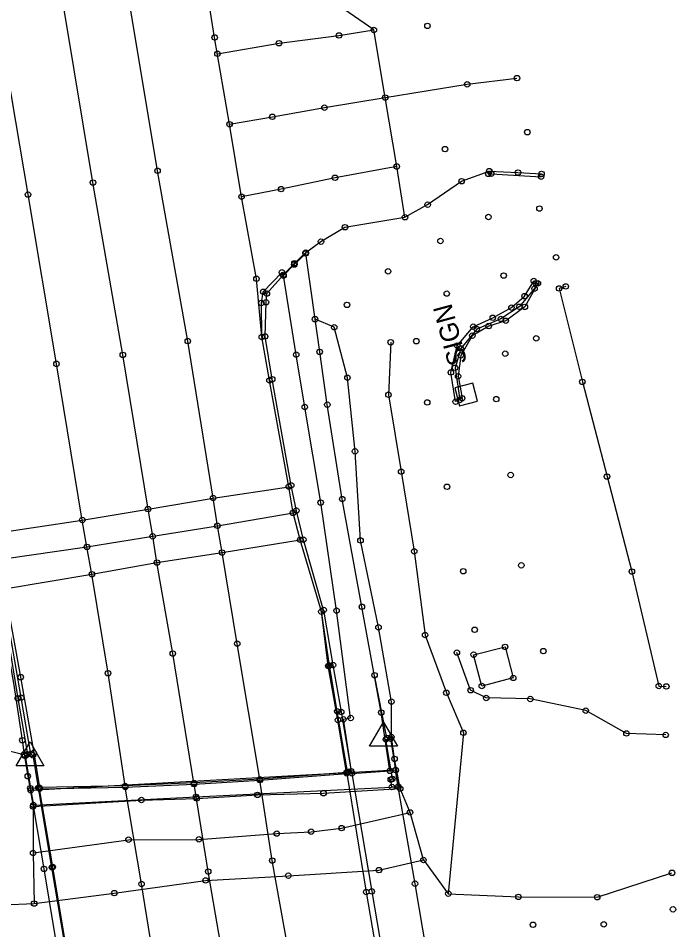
# Model space of a CAD drawing. Extents: x 21481721 to 21494985, y 8063982 to 8084842.
# Drawn here: x 21488058.9 to 21488179.5, y 8075357 to 8075524.3 of the extents above; entities that cross this region are included whole.
import ezdxf

# ---------------------------------------------------------------- set-up
doc = ezdxf.new("R2010")
doc.units = 0
for name, color, linetype in [('Bridge', 7, 'Continuous'), ('Default', 7, 'Continuous'), ('EXT_BL', 7, 'Continuous'), ('EXT_C', 7, 'Continuous'), ('EXT_CON', 7, 'Continuous'), ('EXT_CU', 7, 'Continuous'), ('EXT_D', 7, 'Continuous'), ('EXT_ENT', 7, 'Continuous'), ('EXT_EP', 7, 'Continuous'), ('EXT_GU', 7, 'Continuous'), ('EXT_SWK', 7, 'Continuous'), ('Roadways', 7, 'Continuous'), ('SurControl', 7, 'Continuous'), ('SurPointsNonDTM', 7, 'Continuous'), ('SurRoadPoints', 7, 'Continuous'), ('SurSurveyPoints', 7, 'Continuous'), ('Wall', 7, 'Continuous')]:
    doc.layers.add(name, color=color, linetype=linetype)

msp = doc.modelspace()

# ---------------------------------------------------------------- linework, layer by layer
at = {"layer": 'Bridge'}
for points in [[(21488069.33, 8075343.94), (21488065.2, 8075368.55), (21488062.8, 8075382.91), (21488078.51, 8075383.22), (21488091.12, 8075383.76), (21488103.21, 8075384.48), (21488119.14, 8075385.72), (21488122.72, 8075363.95), (21488125.61, 8075347.18)], [(21488120.08, 8075385.72), (21488123.73, 8075364.06), (21488126.6, 8075347.14), (21488129.6, 8075329.59), (21488132.36, 8075313.39), (21488135.39, 8075295.32), (21488138.2, 8075278.59), (21488141.09, 8075261.71), (21488143.79, 8075245.75), (21488146.67, 8075228.8), (21488149.29, 8075213.2), (21488149.78, 8075209.03)], [(21488108, 8075207.36), (21488103.64, 8075232.31), (21488099.01, 8075261.23), (21488094.1, 8075289.47), (21488089.69, 8075316), (21488085.29, 8075341.96), (21488081.5, 8075365.43), (21488078.51, 8075383.22)], [(21488133.02, 8075208.53), (21488127.97, 8075236.87), (21488123.23, 8075263.68), (21488118.73, 8075292.88), (21488114.06, 8075318.67), (21488109.96, 8075344.62), (21488105.47, 8075369.72), (21488103.21, 8075384.48)], [(21488157.46, 8075212.67), (21488154.44, 8075230.46), (21488151.63, 8075247.26), (21488148.78, 8075264.05), (21488145.96, 8075280.82), (21488143.17, 8075297.55), (21488140.18, 8075315.22), (21488137.31, 8075331.99), (21488134.49, 8075348.81), (21488131.67, 8075365.48), (21488128.59, 8075383.27)], [(21488091.01, 8075206.3), (21488087.47, 8075227.14), (21488083.52, 8075250.23), (21488079.53, 8075273.88), (21488075.57, 8075297.2), (21488071.55, 8075321.1), (21488067.69, 8075343.72), (21488063.6, 8075368.19), (21488061.09, 8075383)], [(21488091.84, 8075206.37), (21488092.44, 8075206.59), (21488088.9, 8075227.4), (21488084.96, 8075250.55), (21488081, 8075274.15), (21488077.07, 8075297.44), (21488073.03, 8075321.28), (21488069.2, 8075343.93), (21488065.05, 8075368.47), (21488062.58, 8075383.09)]]:
    msp.add_lwpolyline(points, dxfattribs=at)
at = {"layer": 'Default'}
msp.add_line((21488061.03, 8075388.55), (21488061.03, 8075388.55), dxfattribs=at)
for points in [[(21488128.12, 8075386.33), (21488061.16, 8075382.6)], [(21488120.76, 8075207.97), (21488116.18, 8075234.47), (21488111.59, 8075262.1), (21488106.7, 8075291.13), (21488102.31, 8075316.99), (21488098.02, 8075342.81), (21488093.73, 8075367.7), (21488091.12, 8075383.76)]]:
    msp.add_lwpolyline(points, dxfattribs=at)
at = {"layer": 'EXT_BL'}
for points in [[(21488103.19, 8075384.64), (21488099.05, 8075409.52), (21488096.27, 8075426.26), (21488095.42, 8075431.16), (21488094.63, 8075436.26), (21488089.97, 8075465.06), (21488084.43, 8075496.32), (21488079.26, 8075527.2), (21488073.87, 8075558.48), (21488069.05, 8075586.55), (21488064.17, 8075616.87), (21488059.01, 8075646.31)], [(21488078.47, 8075383.41), (21488075.34, 8075404.11), (21488072.38, 8075422.27), (21488071.48, 8075427.29), (21488070.62, 8075432.22), (21488065.88, 8075460.89), (21488060.66, 8075491.95), (21488055.28, 8075523.45), (21488049.96, 8075553.99), (21488045.13, 8075582.91), (21488040.13, 8075611.89), (21488034.92, 8075642.89)], [(21488001.98, 8075638.33), (21488003.4, 8075630.75), (21488005.67, 8075621.9), (21488010.36, 8075616.83), (21488017, 8075610.19), (21488020.09, 8075597.51), (21488023.57, 8075574.98), (21488028.19, 8075550.29), (21488031.96, 8075525.57), (21488036.19, 8075501.31), (21488039.36, 8075478.97), (21488044.58, 8075454.12), (21488049.02, 8075430.98), (21488050.89, 8075415.65), (21488053.69, 8075400.59), (21488055.28, 8075390.26), (21488059.93, 8075389.21)], [(21488012.49, 8075527.74), (21488015.17, 8075504.07), (21488014.9, 8075482.37), (21488015.76, 8075463.18), (21488016.7, 8075438.32), (21488019.73, 8075416.24), (21488021.87, 8075392.73), (21488028.33, 8075373.25), (21488035.17, 8075361.28), (21488044.66, 8075361.1), (21488061.79, 8075361.83), (21488076.5, 8075363.75), (21488093.24, 8075366.07), (21488108.43, 8075366.94), (21488125.06, 8075367.97), (21488133.21, 8075369.83), (21488137.78, 8075363.64), (21488150.64, 8075363.06), (21488165.1, 8075362.99), (21488178.82, 8075367.47)], [(21488127.33, 8075392.4), (21488127.35, 8075398.88), (21488124.97, 8075412.53), (21488121.67, 8075428.47), (21488120.66, 8075444.83), (21488119.27, 8075458.34), (21488116.84, 8075467.6), (21488113.33, 8075469.09)], [(21488055.5, 8075419.32), (21488056.08, 8075413.01), (21488057.99, 8075402.29), (21488059.62, 8075391.81), (21488059.93, 8075389.21), (21488060.61, 8075385.21), (21488061.6, 8075379.64), (21488081.48, 8075380.83), (21488091.63, 8075381.12), (21488102.77, 8075381.78), (21488114.88, 8075382.09), (21488128.96, 8075382.93)], [(21488177.67, 8075392.78), (21488170.46, 8075393.05), (21488163, 8075397.24), (21488152.82, 8075399.38), (21488144.73, 8075399.56), (21488141.88, 8075400.99), (21488139.36, 8075407.89)], [(21488133.21, 8075369.83), (21488130.76, 8075378.56), (21488128.96, 8075382.93), (21488127.91, 8075388.38), (21488127.33, 8075392.4), (21488126.53, 8075392.22), (21488124.25, 8075403.74)], [(21488061.6, 8075379.64), (21488061.59, 8075371.11), (21488061.79, 8075361.83)], [(21488061.59, 8075371.11), (21488079.1, 8075373.55), (21488092.01, 8075373.61), (21488106.31, 8075374.67), (21488112.61, 8075375.02), (21488118.2, 8075375.68), (21488130.76, 8075378.56)]]:
    msp.add_lwpolyline(points, dxfattribs=at)
msp.add_lwpolyline([(21488140.32, 8075454.58), (21488139.13, 8075453.95), (21488138.26, 8075459.31), (21488139.43, 8075464.22), (21488142.36, 8075467.71), (21488145.94, 8075469.35), (21488149.37, 8075471.2), (21488151.77, 8075473.31), (21488153.46, 8075476.09), (21488154.22, 8075475.66), (21488151.82, 8075471.35), (21488148.33, 8075468.8), (21488145.19, 8075467.81), (21488142.18, 8075466.05), (21488140.05, 8075462.45), (21488139.57, 8075458.6)], close=True, dxfattribs=at)
at = {"layer": 'EXT_C'}
msp.add_lwpolyline([(21488091.11, 8075383.97), (21488087.22, 8075407.72), (21488084.32, 8075424.42), (21488083.54, 8075429.23), (21488082.68, 8075434.22), (21488078.06, 8075462.54), (21488072.58, 8075494.16), (21488067.41, 8075525.19), (21488062.16, 8075555.92), (21488057.25, 8075584.62), (21488052.2, 8075614.6), (21488046.96, 8075644.54)], dxfattribs=at)
at = {"layer": 'EXT_CON'}
for points in [[(21488107.48, 8075477.19), (21488109.54, 8075479.35), (21488111.61, 8075481.3), (21488114.42, 8075483.32), (21488118.82, 8075485.97), (21488129.83, 8075487.79), (21488128.33, 8075497.11), (21488126.2, 8075509.77), (21488124.12, 8075522.17), (21488112.49, 8075530.26), (21488106.39, 8075529.17), (21488103.72, 8075529.39), (21488101.61, 8075529.97), (21488101.44, 8075533.75), (21488097.85, 8075533.27), (21488097.74, 8075532.79)], [(21488095.42, 8075517.8), (21488106.72, 8075519.73), (21488117.72, 8075521.16), (21488124.12, 8075522.17)], [(21488128.33, 8075497.11), (21488116.99, 8075495.04), (21488107.11, 8075492.96), (21488099.84, 8075491.56)], [(21488055.5, 8075429.95), (21488070.62, 8075432.22), (21488082.68, 8075434.22), (21488094.63, 8075436.26), (21488108.51, 8075438.34)], [(21488056.32, 8075419.59), (21488072.38, 8075422.27), (21488084.32, 8075424.42), (21488096.27, 8075426.26), (21488110.61, 8075428.6)], [(21488128.6, 8075383.26), (21488128.12, 8075386.33), (21488128.11, 8075386.32)], [(21488061.09, 8075383), (21488061.16, 8075382.6), (21488061.65, 8075379.91), (21488091.5, 8075381.41), (21488128.6, 8075383.26)]]:
    msp.add_lwpolyline(points, dxfattribs=at)
for points in [[(21488060.56, 8075389.22), (21488061.21, 8075389.27), (21488059.42, 8075399.63), (21488055.97, 8075419.46), (21488055.5, 8075419.32), (21488058.78, 8075399.49)], [(21488114.49, 8075415.41), (21488114.91, 8075415.7), (21488116.62, 8075405.61), (21488118.14, 8075397), (21488119.95, 8075386.12), (21488119.29, 8075386.03), (21488117.4, 8075397.12), (21488115.96, 8075405.51)], [(21488142.43, 8075407.51), (21488148.2, 8075408.94), (21488149.7, 8075403.24), (21488143.93, 8075401.75)], [(21488128.59, 8075383.27), (21488127.44, 8075383.22), (21488127.23, 8075384.59), (21488127.52, 8075384.72), (21488126.32, 8075391.96), (21488127.19, 8075392.1)], [(21488061.09, 8075383), (21488062.58, 8075383.09), (21488061.58, 8075389.04), (21488060.14, 8075388.93)]]:
    msp.add_lwpolyline(points, close=True, dxfattribs=at)
at = {"layer": 'EXT_CU'}
for points in [[(21488145.28, 8075496.27), (21488145.13, 8075495.75), (21488145.67, 8075495.78), (21488154.81, 8075495.23)], [(21488114.49, 8075415.41), (21488114.91, 8075415.7), (21488111.2, 8075428.61), (21488109.9, 8075433.94), (21488108.96, 8075438.59), (21488105.47, 8075458.06), (21488104.17, 8075465.91), (21488104.33, 8075472.19), (21488104.49, 8075473.78), (21488107.48, 8075477.19)]]:
    msp.add_lwpolyline(points, dxfattribs=at)
at = {"layer": 'EXT_D'}
msp.add_lwpolyline([(21488127.21, 8075464.86), (21488126.79, 8075455.21), (21488129.13, 8075441.11), (21488131.52, 8075426.48), (21488133.52, 8075411.12), (21488137.42, 8075400.51), (21488140.55, 8075393.17), (21488137.78, 8075363.64)], dxfattribs=at)
at = {"layer": 'EXT_ENT'}
msp.add_lwpolyline([(21488097.64, 8075504.87), (21488105.5, 8075506.23), (21488115.05, 8075507.91), (21488126.2, 8075509.77), (21488141.25, 8075512.19), (21488150.38, 8075513.33)], dxfattribs=at)
at = {"layer": 'EXT_EP'}
for points in [[(21488129.83, 8075487.79), (21488133.99, 8075490.11), (21488140.22, 8075494.41), (21488145.28, 8075496.27), (21488150.56, 8075496), (21488154.89, 8075495.76)], [(21488159.33, 8075475.1), (21488158.11, 8075474.73), (21488162.38, 8075457.57), (21488166.9, 8075440.2), (21488171.47, 8075422.77), (21488176.39, 8075401.75), (21488177.78, 8075401.68)], [(21488056.32, 8075419.59), (21488059.31, 8075403.38), (21488061.71, 8075389.47), (21488062.76, 8075383.11)], [(21488119.11, 8075385.91), (21488103.19, 8075384.64), (21488091.11, 8075383.97), (21488078.47, 8075383.41), (21488062.76, 8075383.11)]]:
    msp.add_lwpolyline(points, dxfattribs=at)
at = {"layer": 'EXT_GU'}
for points in [[(21488103.55, 8075465.82), (21488102.57, 8075476.5), (21488099.84, 8075491.56), (21488097.64, 8075504.87), (21488094.91, 8075520.79), (21488092.51, 8075535.93)], [(21488119.11, 8075385.91), (21488117.53, 8075395.53), (21488115.75, 8075405.44), (21488114.49, 8075415.41), (21488110.61, 8075428.6), (21488109.29, 8075433.53), (21488108.51, 8075438.34), (21488104.96, 8075457.86), (21488103.55, 8075465.82), (21488103.48, 8075472.05), (21488103.82, 8075474.11), (21488107.24, 8075477.68), (21488107.48, 8075477.19)]]:
    msp.add_lwpolyline(points, dxfattribs=at)
at = {"layer": 'EXT_SWK'}
for points in [[(21488120.08, 8075385.72), (21488118.53, 8075395.65), (21488119.86, 8075395.89), (21488117.28, 8075415.59), (21488114.36, 8075435.43), (21488111.44, 8075452.96), (21488109.88, 8075462.57), (21488107.55, 8075477.09), (21488109.52, 8075479.12), (21488111.61, 8075481.15)], [(21488120.08, 8075385.72), (21488127.06, 8075386.19), (21488125.48, 8075396.88), (21488121.92, 8075416.3), (21488118.32, 8075436.07), (21488115.58, 8075453.4), (21488114.18, 8075463.09), (21488111.61, 8075481.15)]]:
    msp.add_lwpolyline(points, dxfattribs=at)
at = {"layer": 'Roadways'}
msp.add_lwpolyline([(21488055.81, 8075425.01), (21488071.48, 8075427.29), (21488083.54, 8075429.23), (21488095.42, 8075431.16), (21488109.29, 8075433.53)], dxfattribs=at)
at = {"layer": 'SurControl'}
for points in [[(21488125.9, 8075395.11), (21488128.44, 8075390.7), (21488123.35, 8075390.7)], [(21488061.03, 8075391.49), (21488063.58, 8075387.08), (21488058.49, 8075387.08)]]:
    msp.add_lwpolyline(points, close=True, dxfattribs=at)
at = {"layer": 'SurPointsNonDTM'}
for centre in [(21488153.61, 8075474.69), (21488153.86, 8075475.69), (21488150.81, 8075471.37), (21488147.43, 8075469.13), (21488142.99, 8075467.27), (21488140.06, 8075463.72), (21488139.01, 8075460.16), (21488139.89, 8075454.24), (21488103.21, 8075384.48), (21488103.21, 8075384.48), (21488119.14, 8075385.72), (21488119.14, 8075385.72), (21488120.08, 8075385.72), (21488061.09, 8075383), (21488062.58, 8075383.09), (21488062.8, 8075382.91), (21488078.51, 8075383.22), (21488078.51, 8075383.22), (21488091.12, 8075383.76), (21488091.12, 8075383.76), (21488128.59, 8075383.27), (21488105.47, 8075369.72), (21488063.6, 8075368.19), (21488065.05, 8075368.47), (21488065.2, 8075368.55), (21488093.73, 8075367.7), (21488081.5, 8075365.43), (21488131.67, 8075365.48), (21488122.72, 8075363.95), (21488123.73, 8075364.06)]:
    msp.add_circle(centre, 0.5, dxfattribs=at)
at = {"layer": 'SurRoadPoints'}
msp.add_lwpolyline([(21488142.7, 8075455.71), (21488142.7, 8075455.71), (21488142.26, 8075457.36), (21488138.95, 8075456.47), (21488139.84, 8075453.16), (21488143.15, 8075454.05), (21488142.7, 8075455.71)], dxfattribs=at)
at = {"layer": 'SurSurveyPoints'}
for centre in [(21488124.12, 8075522.17), (21488124.12, 8075522.17), (21488133.95, 8075522.92), (21488094.91, 8075520.79), (21488117.72, 8075521.16), (21488106.72, 8075519.73), (21488095.42, 8075517.8), (21488150.38, 8075513.33), (21488141.25, 8075512.19), (21488126.2, 8075509.77), (21488126.2, 8075509.77), (21488126.2, 8075509.77), (21488115.05, 8075507.91), (21488097.64, 8075504.87), (21488097.64, 8075504.87), (21488105.5, 8075506.23), (21488152.29, 8075503.41), (21488137.18, 8075500.3), (21488128.33, 8075497.11), (21488128.33, 8075497.11), (21488084.43, 8075496.32), (21488116.99, 8075495.04), (21488145.13, 8075495.75), (21488145.28, 8075496.27), (21488145.28, 8075496.27), (21488145.67, 8075495.78), (21488150.56, 8075496), (21488154.81, 8075495.23), (21488154.89, 8075495.76), (21488072.58, 8075494.16), (21488140.22, 8075494.41), (21488060.66, 8075491.95), (21488099.84, 8075491.56), (21488099.84, 8075491.56), (21488107.11, 8075492.96), (21488133.99, 8075490.11), (21488154.51, 8075489.39), (21488129.83, 8075487.79), (21488129.83, 8075487.79), (21488145.15, 8075487.85), (21488118.82, 8075485.97), (21488114.42, 8075483.32), (21488136.33, 8075483.43), (21488111.61, 8075481.3), (21488111.61, 8075481.15), (21488111.61, 8075481.15), (21488157.56, 8075480.43), (21488109.52, 8075479.12), (21488109.54, 8075479.35), (21488102.57, 8075476.5), (21488107.24, 8075477.68), (21488107.48, 8075477.19), (21488107.48, 8075477.19), (21488107.48, 8075477.19), (21488107.55, 8075477.09), (21488126.74, 8075477.86), (21488147.93, 8075477.09), (21488153.46, 8075476.09), (21488154.22, 8075475.66), (21488158.11, 8075474.73), (21488159.33, 8075475.1), (21488103.82, 8075474.11), (21488104.49, 8075473.78), (21488137.49, 8075473.78), (21488151.77, 8075473.31), (21488103.48, 8075472.05), (21488104.33, 8075472.19), (21488119.19, 8075471.71), (21488151.82, 8075471.35), (21488149.37, 8075471.2), (21488113.33, 8075469.09), (21488145.94, 8075469.35), (21488148.33, 8075468.8), (21488116.84, 8075467.6), (21488142.36, 8075467.71), (21488145.19, 8075467.81), (21488089.97, 8075465.06), (21488103.55, 8075465.82), (21488103.55, 8075465.82), (21488104.17, 8075465.91), (21488127.21, 8075464.86), (21488131.91, 8075465.05), (21488142.18, 8075466.05), (21488153.91, 8075465.58), (21488114.18, 8075463.09), (21488139.43, 8075464.22), (21488078.06, 8075462.54), (21488109.88, 8075462.57), (21488140.05, 8075462.45), (21488148.23, 8075462.75), (21488065.88, 8075460.89), (21488105.47, 8075458.06), (21488119.27, 8075458.34), (21488138.26, 8075459.31), (21488139.57, 8075458.6), (21488104.96, 8075457.86), (21488162.38, 8075457.57), (21488126.79, 8075455.21), (21488140.32, 8075454.58), (21488140.32, 8075454.58), (21488111.44, 8075452.96), (21488115.58, 8075453.4), (21488133.91, 8075453.81), (21488139.13, 8075453.95), (21488146.58, 8075454.41), (21488120.66, 8075444.83), (21488129.13, 8075441.11), (21488149.23, 8075440.48), (21488166.9, 8075440.2), (21488108.51, 8075438.34), (21488108.96, 8075438.59), (21488137.55, 8075438.32), (21488094.63, 8075436.26), (21488114.36, 8075435.43), (21488118.32, 8075436.07), (21488082.68, 8075434.22), (21488109.29, 8075433.53), (21488109.9, 8075433.94), (21488070.62, 8075432.22), (21488095.42, 8075431.16), (21488083.54, 8075429.23), (21488110.61, 8075428.6), (21488111.2, 8075428.61), (21488121.67, 8075428.47), (21488071.48, 8075427.29), (21488096.27, 8075426.26), (21488131.52, 8075426.48), (21488084.32, 8075424.42), (21488140.51, 8075422.82), (21488151.17, 8075423.9), (21488072.38, 8075422.27), (21488171.47, 8075422.77), (21488121.92, 8075416.3), (21488114.49, 8075415.41), (21488114.49, 8075415.41), (21488114.49, 8075415.41), (21488114.49, 8075415.41), (21488114.91, 8075415.7), (21488114.91, 8075415.7), (21488117.28, 8075415.59), (21488124.97, 8075412.53), (21488133.52, 8075411.12), (21488142.61, 8075412.08), (21488099.05, 8075409.52), (21488139.36, 8075407.89), (21488148.2, 8075408.94), (21488155.21, 8075408.17), (21488087.22, 8075407.72), (21488142.43, 8075407.51), (21488142.43, 8075407.51), (21488115.75, 8075405.44), (21488115.96, 8075405.51), (21488116.62, 8075405.61), (21488059.31, 8075403.38), (21488075.34, 8075404.11), (21488124.25, 8075403.74), (21488149.7, 8075403.24), (21488143.93, 8075401.75), (21488176.39, 8075401.75), (21488177.78, 8075401.68), (21488058.78, 8075399.49), (21488059.42, 8075399.63), (21488137.42, 8075400.51), (21488141.88, 8075400.99), (21488144.73, 8075399.56), (21488152.82, 8075399.38), (21488127.35, 8075398.88), (21488117.4, 8075397.12), (21488118.14, 8075397), (21488125.48, 8075396.88), (21488163, 8075397.24), (21488117.53, 8075395.53), (21488118.53, 8075395.65), (21488119.86, 8075395.89), (21488140.55, 8075393.17), (21488170.46, 8075393.05), (21488177.67, 8075392.78), (21488059.62, 8075391.81), (21488126.32, 8075391.96), (21488126.53, 8075392.22), (21488127.19, 8075392.1), (21488127.33, 8075392.4), (21488127.33, 8075392.4), (21488061.71, 8075389.47), (21488059.93, 8075389.21), (21488059.93, 8075389.21), (21488060.14, 8075388.93), (21488060.56, 8075389.22), (21488060.56, 8075389.22), (21488061.21, 8075389.27), (21488061.58, 8075389.04), (21488127.91, 8075388.38), (21488119.29, 8075386.03), (21488119.95, 8075386.12), (21488127.06, 8075386.19), (21488128.11, 8075386.32), (21488128.12, 8075386.33), (21488060.61, 8075385.21), (21488103.19, 8075384.64), (21488103.19, 8075384.64), (21488119.11, 8075385.91), (21488119.11, 8075385.91), (21488120.08, 8075385.72), (21488120.08, 8075385.72), (21488127.23, 8075384.59), (21488127.52, 8075384.72), (21488061.09, 8075383), (21488061.09, 8075383), (21488061.09, 8075383), (21488062.58, 8075383.09), (21488062.76, 8075383.11), (21488062.76, 8075383.11), (21488078.47, 8075383.41), (21488078.47, 8075383.41), (21488091.11, 8075383.97), (21488091.11, 8075383.97), (21488127.44, 8075383.22), (21488128.59, 8075383.27), (21488128.59, 8075383.27), (21488128.6, 8075383.26), (21488128.6, 8075383.26), (21488128.96, 8075382.93), (21488128.96, 8075382.93), (21488061.16, 8075382.6), (21488091.5, 8075381.41), (21488091.63, 8075381.12), (21488102.77, 8075381.78), (21488114.88, 8075382.09), (21488061.6, 8075379.64), (21488061.6, 8075379.64), (21488061.65, 8075379.91), (21488081.48, 8075380.83), (21488130.76, 8075378.56), (21488130.76, 8075378.56), (21488106.31, 8075374.67), (21488112.61, 8075375.02), (21488118.2, 8075375.68), (21488079.1, 8075373.55), (21488092.01, 8075373.61), (21488061.59, 8075371.11), (21488133.21, 8075369.83), (21488133.21, 8075369.83), (21488133.21, 8075369.83), (21488133.21, 8075369.83), (21488125.06, 8075367.97), (21488093.24, 8075366.07), (21488108.43, 8075366.94), (21488178.82, 8075367.47), (21488076.5, 8075363.75), (21488137.78, 8075363.64), (21488137.78, 8075363.64), (21488150.64, 8075363.06), (21488165.1, 8075362.99), (21488061.79, 8075361.83), (21488061.79, 8075361.83), (21488179.01, 8075360.76), (21488153.32, 8075357.94), (21488166.3, 8075358.02)]:
    msp.add_circle(centre, 0.5, dxfattribs=at)
at = {"layer": 'Wall'}
msp.add_lwpolyline([(21488153.86, 8075475.69), (21488153.61, 8075474.69), (21488150.81, 8075471.37), (21488147.43, 8075469.13), (21488142.99, 8075467.27), (21488140.06, 8075463.72), (21488139.01, 8075460.16), (21488139.89, 8075454.24)], dxfattribs=at)

# ---------------------------------------------------------------- texts
at = {"layer": 'SurRoadPoints'}
msp.add_text('SIGN', height=3.498, rotation=105.1071, dxfattribs=at).set_placement((21488141.28, 8075461.13))

doc.saveas('drawing.dxf')
